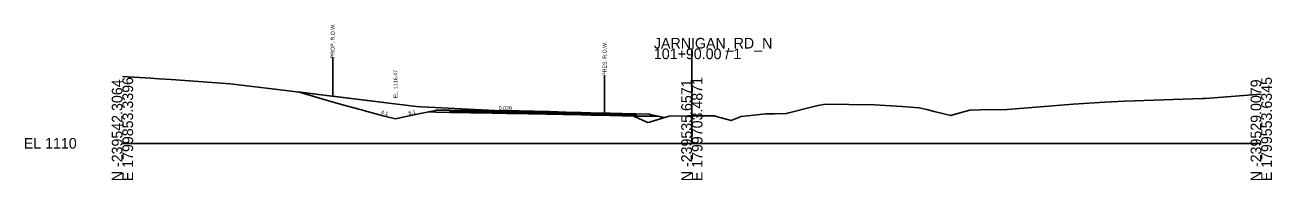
# Model space of a CAD drawing. Extents: x 214513 to 217151, y 214739 to 216780.
# Drawn here: x 216122.7 to 216451.2, y 216738.7 to 216779.6 of the extents above; entities that cross this region are included whole.
import ezdxf

# ---------------------------------------------------------------- set-up
doc = ezdxf.new("R2010")
doc.units = 0
for name, color, linetype in [('CONCEPT - TRANSPORTATION - Roads Text', 7, 'Continuous'), ('DESIGN - CENTERLINE - Proposed', 7, 'Continuous'), ('DESIGN - DRAINAGE - Special Ditches', 7, 'Continuous'), ('DESIGN - EARTHWORK - Shapes', 7, 'Continuous'), ('DESIGN - ROW - Right-of-Way Linework', 7, 'Continuous'), ('DESIGN - TRANSPORTATION - Text', 7, 'Continuous'), ('FUNCTIONAL - ROW - Right-of-Way Text', 7, 'Continuous'), ('Section', 7, 'Continuous'), ('SURVEY - DTM GRAPHICS - Triangles', 7, 'Continuous'), ('SURVEY - PROPERTY - ROW Lines', 7, 'Continuous'), ('XSCell', 7, 'Continuous')]:
    doc.layers.add(name, color=color, linetype=linetype)

msp = doc.modelspace()

# ---------------------------------------------------------------- linework, layer by layer
at = {"layer": 'DESIGN - DRAINAGE - Special Ditches'}
for points in [[(216194.64, 216761.91), (216200.87, 216760.1), (216202.62, 216759.58), (216207.68, 216758.18), (216210.95, 216757.26), (216213.21, 216756.67), (216217.02, 216755.65), (216217.77, 216755.47), (216220.27, 216754.84)], [(216231.16, 216757.07), (216230.94, 216757.03), (216226.84, 216756.25), (216222.25, 216755.29), (216220.27, 216754.84)], [(216234.65, 216757.08), (216234.65, 216756.83), (216234.65, 216756.5), (216234.65, 216756.5), (216230.94, 216756.62), (216229.06, 216756.67), (216230.94, 216757.03), (216231.16, 216757.07), (216234.65, 216757.08), (216234.65, 216757.08)], [(216234.65, 216757.08), (216236.57, 216757.06), (216238.3, 216757.03), (216239.92, 216757.01), (216241.85, 216756.98), (216249.63, 216756.83), (216252.62, 216756.78), (216255.3, 216756.73), (216257.76, 216756.68), (216260.08, 216756.64), (216262.32, 216756.6), (216264.55, 216756.56), (216266.82, 216756.51), (216269.2, 216756.46), (216271.76, 216756.4), (216274.16, 216756.34), (216276.85, 216756.28), (216279.96, 216756.2), (216283.66, 216756.1)], [(216283.66, 216756.1), (216283.66, 216756), (216279.96, 216756.1), (216276.85, 216756.18), (216274.16, 216756.24), (216271.76, 216756.3), (216269.2, 216756.36), (216266.82, 216756.41), (216264.55, 216756.46), (216262.32, 216756.5), (216260.08, 216756.54), (216257.76, 216756.58), (216255.3, 216756.63), (216252.62, 216756.68), (216249.63, 216756.73), (216241.85, 216756.88), (216239.92, 216756.91), (216238.3, 216756.93), (216236.57, 216756.96), (216234.65, 216756.98), (216234.65, 216757.08), (216236.57, 216757.06), (216238.3, 216757.03), (216239.92, 216757.01), (216241.85, 216756.98), (216249.63, 216756.83), (216252.62, 216756.78), (216255.3, 216756.73), (216257.76, 216756.68), (216260.08, 216756.64), (216262.32, 216756.6), (216264.55, 216756.56), (216266.82, 216756.51), (216269.2, 216756.46), (216271.76, 216756.4), (216274.16, 216756.34), (216276.85, 216756.28), (216279.96, 216756.2), (216283.66, 216756.1)], [(216283.66, 216756), (216283.66, 216755.85), (216279.96, 216755.95), (216276.85, 216756.03), (216274.16, 216756.09), (216271.76, 216756.15), (216269.2, 216756.21), (216266.82, 216756.26), (216264.55, 216756.31), (216262.32, 216756.35), (216260.08, 216756.39), (216257.76, 216756.43), (216255.3, 216756.48), (216252.62, 216756.53), (216249.63, 216756.58), (216241.85, 216756.73), (216239.92, 216756.76), (216238.3, 216756.78), (216236.57, 216756.81), (216234.65, 216756.83), (216234.65, 216756.98), (216236.57, 216756.96), (216238.3, 216756.93), (216239.92, 216756.91), (216241.85, 216756.88), (216249.63, 216756.73), (216252.62, 216756.68), (216255.3, 216756.63), (216257.76, 216756.58), (216260.08, 216756.54), (216262.32, 216756.5), (216264.55, 216756.46), (216266.82, 216756.41), (216269.2, 216756.36), (216271.76, 216756.3), (216274.16, 216756.24), (216276.85, 216756.18), (216279.96, 216756.1), (216283.66, 216756)], [(216283.66, 216755.85), (216283.66, 216755.52), (216279.96, 216755.62), (216276.85, 216755.7), (216274.16, 216755.76), (216271.76, 216755.82), (216269.2, 216755.88), (216266.82, 216755.93), (216264.55, 216755.98), (216262.32, 216756.02), (216260.08, 216756.06), (216257.76, 216756.1), (216255.3, 216756.15), (216252.62, 216756.2), (216249.63, 216756.25), (216241.85, 216756.4), (216239.92, 216756.43), (216238.3, 216756.45), (216236.57, 216756.48), (216234.65, 216756.5), (216234.65, 216756.83), (216236.57, 216756.81), (216238.3, 216756.78), (216239.92, 216756.76), (216241.85, 216756.73), (216249.63, 216756.58), (216252.62, 216756.53), (216255.3, 216756.48), (216257.76, 216756.43), (216260.08, 216756.39), (216262.32, 216756.35), (216264.55, 216756.31), (216266.82, 216756.26), (216269.2, 216756.21), (216271.76, 216756.15), (216274.16, 216756.09), (216276.85, 216756.03), (216279.96, 216755.95), (216283.66, 216755.85)], [(216289.26, 216755.56), (216287.37, 216755.55), (216283.66, 216755.52), (216283.66, 216755.52), (216283.66, 216755.85), (216283.66, 216756.1), (216283.66, 216756.1), (216287.16, 216756.01), (216287.37, 216755.96), (216289.26, 216755.56)], [(216291.19, 216755.15), (216287.37, 216755.96), (216287.16, 216756.01)]]:
    msp.add_lwpolyline(points, dxfattribs=at)
at = {"layer": 'DESIGN - EARTHWORK - Shapes'}
for p, q in [((216234.65, 216757.08), (216231.16, 216757.07)), ((216234.65, 216757.08), (216236.57, 216757.06)), ((216234.65, 216756.98), (216234.65, 216757.08)), ((216234.65, 216756.83), (216234.65, 216756.98)), ((216234.65, 216756.98), (216236.57, 216756.96)), ((216234.65, 216756.5), (216234.65, 216756.83)), ((216234.65, 216756.83), (216234.65, 216756.5)), ((216236.57, 216757.06), (216238.3, 216757.03)), ((216236.57, 216756.96), (216238.3, 216756.93)), ((216238.3, 216757.03), (216239.92, 216757.01)), ((216238.3, 216756.93), (216239.92, 216756.91)), ((216238.3, 216756.78), (216239.92, 216756.76)), ((216241.85, 216756.98), (216239.92, 216757.01)), ((216239.92, 216756.76), (216241.85, 216756.73)), ((216242.86, 216756.96), (216241.85, 216756.98)), ((216242.86, 216756.96), (216244.42, 216756.93)), ((216244.42, 216756.93), (216242.86, 216756.96)), ((216244.42, 216756.93), (216249.63, 216756.83)), ((216249.63, 216756.83), (216244.42, 216756.93)), ((216255.3, 216756.63), (216257.76, 216756.58)), ((216255.3, 216756.48), (216257.76, 216756.43)), ((216257.76, 216756.58), (216260.08, 216756.54)), ((216257.76, 216756.43), (216260.08, 216756.39)), ((216260.08, 216756.64), (216262.32, 216756.6)), ((216260.08, 216756.54), (216262.32, 216756.5)), ((216262.32, 216756.35), (216260.08, 216756.39)), ((216262.32, 216756.5), (216264.55, 216756.46)), ((216264.55, 216756.31), (216266.82, 216756.26)), ((216272.02, 216756.29), (216266.29, 216756.52)), ((216269.2, 216756.21), (216266.82, 216756.26)), ((216266.82, 216756.26), (216269.2, 216756.21)), ((216271.76, 216756.3), (216269.2, 216756.36)), ((216269.2, 216756.36), (216271.76, 216756.3)), ((216272.02, 216756.29), (216271.76, 216756.3)), ((216271.76, 216756.3), (216272.02, 216756.29)), ((216279.96, 216755.95), (216276.85, 216756.03)), ((216282.32, 216755.89), (216279.96, 216755.95)), ((216279.96, 216755.95), (216282.32, 216755.89)), ((216283.07, 216755.54), (216282.32, 216755.89)), ((216283.66, 216755.52), (216283.07, 216755.54)), ((216283.07, 216755.54), (216286.3, 216754.02)), ((216291.19, 216755.15), (216289.26, 216755.56))]:
    msp.add_line(p, q, dxfattribs=at)
for points in [[(216266.29, 216756.52), (216260.89, 216756.73), (216252.87, 216756.89), (216246.5, 216757.01), (216227.16, 216757.96), (216225.78, 216758.05), (216220.05, 216758.79), (216203.74, 216760.79), (216201.44, 216761.07), (216194.64, 216761.91)], [(216194.64, 216761.91), (216200.87, 216760.1), (216202.62, 216759.58), (216207.68, 216758.18), (216210.95, 216757.26), (216213.21, 216756.67), (216217.02, 216755.65), (216217.77, 216755.47), (216220.27, 216754.84)], [(216220.27, 216754.84), (216222.25, 216755.29), (216226.84, 216756.25), (216229.06, 216756.67)], [(216229.06, 216756.67), (216230.94, 216757.03), (216231.16, 216757.07), (216234.65, 216757.08)], [(216231.16, 216757.07), (216230.94, 216757.03), (216229.06, 216756.67), (216230.94, 216756.62), (216234.65, 216756.5)], [(216229.06, 216756.67), (216229.06, 216756.67)], [(216239.92, 216757.01), (216238.3, 216757.03), (216236.57, 216757.06), (216234.65, 216757.08), (216234.65, 216756.98)], [(216236.57, 216756.96), (216234.65, 216756.98), (216234.65, 216756.83)], [(216239.92, 216756.76), (216238.3, 216756.78), (216236.57, 216756.81), (216234.65, 216756.83)], [(216234.65, 216756.83), (216236.57, 216756.81), (216238.3, 216756.78)], [(216234.65, 216756.5), (216236.57, 216756.48), (216238.3, 216756.45), (216239.92, 216756.43), (216241.85, 216756.4), (216249.63, 216756.25), (216252.62, 216756.2), (216255.3, 216756.15), (216257.76, 216756.1), (216260.08, 216756.06), (216262.32, 216756.02), (216264.55, 216755.98), (216266.82, 216755.93), (216269.2, 216755.88), (216271.76, 216755.82), (216274.16, 216755.76), (216276.85, 216755.7), (216279.96, 216755.62), (216283.07, 216755.54)], [(216239.92, 216756.91), (216238.3, 216756.93), (216236.57, 216756.96)], [(216239.92, 216757.01), (216241.85, 216756.98), (216242.86, 216756.96)], [(216257.76, 216756.58), (216255.3, 216756.63), (216252.62, 216756.68), (216249.63, 216756.73), (216241.85, 216756.88), (216239.92, 216756.91)], [(216239.92, 216756.91), (216241.85, 216756.88), (216249.63, 216756.73)], [(216260.08, 216756.39), (216257.76, 216756.43), (216255.3, 216756.48), (216252.62, 216756.53), (216249.63, 216756.58), (216241.85, 216756.73), (216239.92, 216756.76)], [(216241.85, 216756.73), (216249.63, 216756.58), (216252.62, 216756.53), (216255.3, 216756.48)], [(216249.63, 216756.83), (216252.62, 216756.78), (216255.3, 216756.73), (216257.76, 216756.68), (216260.08, 216756.64)], [(216255.3, 216756.73), (216252.62, 216756.78), (216249.63, 216756.83)], [(216249.63, 216756.73), (216252.62, 216756.68), (216255.3, 216756.63)], [(216262.32, 216756.6), (216260.08, 216756.64), (216257.76, 216756.68), (216255.3, 216756.73)], [(216264.55, 216756.46), (216262.32, 216756.5), (216260.08, 216756.54), (216257.76, 216756.58)], [(216260.08, 216756.39), (216262.32, 216756.35), (216264.55, 216756.31)], [(216262.32, 216756.6), (216264.55, 216756.56), (216266.29, 216756.52)], [(216266.29, 216756.52), (216264.55, 216756.56), (216262.32, 216756.6)], [(216266.82, 216756.26), (216264.55, 216756.31), (216262.32, 216756.35)], [(216269.2, 216756.36), (216266.82, 216756.41), (216264.55, 216756.46)], [(216264.55, 216756.46), (216266.82, 216756.41), (216269.2, 216756.36)], [(216276.85, 216756.03), (216274.16, 216756.09), (216271.76, 216756.15), (216269.2, 216756.21)], [(216269.2, 216756.21), (216271.76, 216756.15), (216274.16, 216756.09)], [(216282.32, 216755.89), (216282.31, 216755.89), (216280.55, 216756.01), (216276.17, 216756.13), (216272.02, 216756.29)], [(216274.16, 216756.09), (216276.85, 216756.03), (216279.96, 216755.95)], [(216289.26, 216755.56), (216287.37, 216755.55), (216283.66, 216755.52)], [(216286.3, 216754.02), (216286.67, 216753.85), (216287.17, 216753.98), (216291.19, 216755.15)], [(216289.26, 216755.56), (216289.26, 216755.56)]]:
    msp.add_lwpolyline(points, dxfattribs=at)
at = {"layer": 'DESIGN - ROW - Right-of-Way Linework'}
msp.add_lwpolyline([(216203.74, 216770.79), (216203.74, 216760.79)], dxfattribs=at)
at = {"layer": 'FUNCTIONAL - ROW - Right-of-Way Text'}
for p, q in [((216244.42, 216756.93), (216242.86, 216756.96)), ((216269.03, 216756.46), (216267.68, 216756.49))]:
    msp.add_line(p, q, dxfattribs=at)
at = {"layer": 'SURVEY - DTM GRAPHICS - Triangles'}
msp.add_lwpolyline([(216148.36, 216766.01), (216155.81, 216765.51), (216157.92, 216765.33), (216161.22, 216765.15), (216176.73, 216764.02), (216188.46, 216762.67), (216201.44, 216761.07), (216220.05, 216758.79), (216225.78, 216758.05), (216227.16, 216757.96), (216246.5, 216757.01), (216252.87, 216756.89), (216260.89, 216756.73), (216276.17, 216756.13), (216280.55, 216756.01), (216282.31, 216755.89), (216286.3, 216754.02), (216286.67, 216753.85), (216287.17, 216753.98), (216292.41, 216755.51), (216297.45, 216755.61), (216298.67, 216755.65), (216303.6, 216755.58), (216304.31, 216755.58), (216305.1, 216755.35), (216308.68, 216754.38), (216310.5, 216755.11), (216311.36, 216755.44), (216314.67, 216755.77), (216317.85, 216756.16), (216320.1, 216756.18), (216323.21, 216756.22), (216330.47, 216758.08), (216331.6, 216758.37), (216332.04, 216758.44), (216333.56, 216758.67), (216339.74, 216758.6), (216346.45, 216758.53), (216353.72, 216758.04), (216358.15, 216757.73), (216358.56, 216757.65), (216360.27, 216757.25), (216362.22, 216756.78), (216366.58, 216755.67), (216369.28, 216756.45), (216371.59, 216757.15), (216374.44, 216757.16), (216381.45, 216757.25), (216398.78, 216758.68), (216407.16, 216759.2), (216412.29, 216759.5), (216432.88, 216760.14), (216433.6, 216760.2), (216448.36, 216761.31)], dxfattribs=at)
at = {"layer": 'SURVEY - PROPERTY - ROW Lines'}
msp.add_lwpolyline([(216275.38, 216766.16), (216275.38, 216756.16)], dxfattribs=at)
at = {"layer": 'XSCell'}
for p, q in [((216298.36, 216748.36), (216298.36, 216773.36)), ((216148.36, 216748.36), (216298.36, 216748.36)), ((216298.36, 216748.36), (216448.36, 216748.36))]:
    msp.add_line(p, q, dxfattribs=at)

# ---------------------------------------------------------------- texts
at = {"layer": 'CONCEPT - TRANSPORTATION - Roads Text'}
msp.add_text('0.020', height=1, rotation=358.8542, dxfattribs=at).set_placement((216247.46, 216757.18))
at = {"layer": 'DESIGN - CENTERLINE - Proposed'}
for s, rotation, p in [('EL. 1116.47', 90, (216220.77, 216760.23)), ('4:1', 345.7611, (216216.39, 216756.13)), ('5:1', 11.5399, (216223.81, 216755.8))]:
    msp.add_text(s, height=1, rotation=rotation, dxfattribs=at).set_placement(p)
at = {"layer": 'DESIGN - TRANSPORTATION - Text'}
for s, p in [('PROP. R.O.W.', (216204.24, 216770.79)), ('PRES. R.O.W.', (216275.88, 216766.16))]:
    msp.add_text(s, height=1, rotation=90, dxfattribs=at).set_placement(p)
at = {"layer": 'Section'}
msp.add_text('-', height=0.0001, dxfattribs=at).set_placement((216148.36, 216748.36))
at = {"layer": 'XSCell'}
for s, p in [('JARNIGAN_RD_N', (216288.36, 216773.36)), ('101+90.00 / 1', (216288.36, 216770.56)), ('EL 1110', (216122.36, 216746.96))]:
    msp.add_text(s, height=2.8, dxfattribs=at).set_placement(p)
for s, p in [('N -239542.3064', (216148.36, 216738.36)), ('E 1799853.3396', (216151.16, 216738.36)), ('N -239535.6571', (216298.36, 216738.36)), ('E 1799703.4871', (216301.16, 216738.36)), ('N -239529.0079', (216448.36, 216738.36)), ('E 1799553.6345', (216451.16, 216738.36))]:
    msp.add_text(s, height=2.8, rotation=90, dxfattribs=at).set_placement(p)

doc.saveas('drawing.dxf')
